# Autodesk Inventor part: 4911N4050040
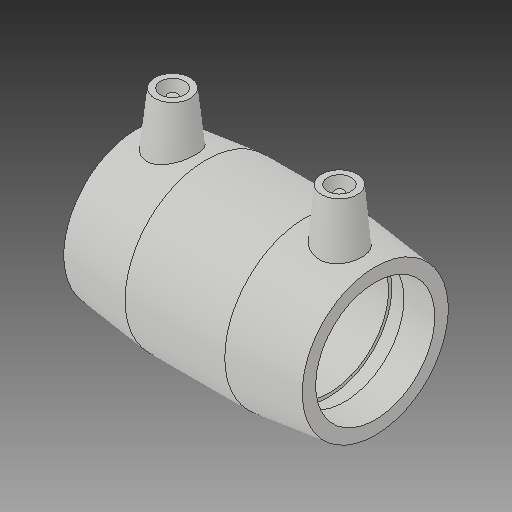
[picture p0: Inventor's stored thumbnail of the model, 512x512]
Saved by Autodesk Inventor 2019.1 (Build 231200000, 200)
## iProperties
Created: 2017-06
Part Number: 4911N4050040
Material: Generic
Description: PLASSON ASTM REDUCING COUPLING ADAPTOR 50-1 1/2''
Document SubType Name: Modeling
Designer: KIM
Mass: 54.8237 g
Surface Area: 155.252 cm^2
Volume: 54.8237 cm^3
Density: 1 g/cm^3
Appearance: Default
Author: KIM
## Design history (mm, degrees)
derived "4911N.ipt"
feature "Solid1::4911N.ipt"
tag "TaggingFeature1"
body "Solid1"
other parameters: "d0" = 100.076, "d2" = 68.072, "d3" = 48.514, "d4" = 29.1084, "d5" = 61.2648, "d7" = 48.1, "d8" = 168 deg, "d10" = 19.4056, "d11" = 6.46853, "d14" = 17.6296, "d22" = 108.92847, "d29" = 53.086, "d30" = 15, "d31" = 35.0266, "d34" = 6 deg, "d41" = 4, "d42" = 14, "d43" = 0, "d48" = 68.072, "d50" = 68.072, "d52" = 43.29, "d53" = 19.4056, "d54" = 6.46853, "d55" = 168 deg, "d56" = 29.1084, "d57" = 48.514, "d58" = 61.2648, "d59" = 2.4257, "d60" = 135 deg, "d61" = 53.086, "d62" = 15, "d64" = 4, "d66" = 5 deg, "d67" = 14, "d68" = 0, "d69" = 35.0266, "d95" = 3, "d96" = 0, "d97" = 3, "d98" = 0, "d_1" = 48.1, "L_" = 100.076, "L_2" = 48.514, "D_1" = 68.072, "A_1" = 53.086, "d_2" = 12, "L_1" = 48.514, "A_" = 53.086, "D_" = 68.072
